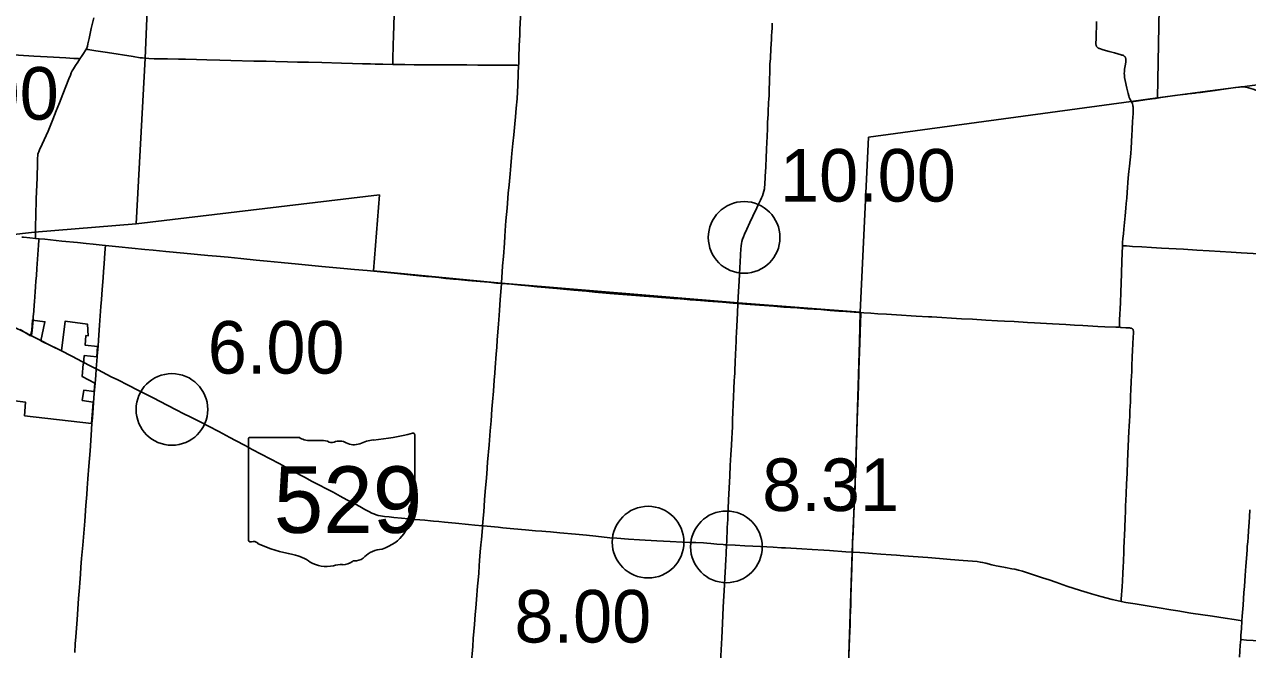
# Model space of a CAD drawing. Extents: x 1813937 to 1948437, y 826606 to 1022856.
# Drawn here: x 1864595 to 1890191, y 901785 to 914870 of the extents above; entities that cross this region are included whole.
import ezdxf

# ---------------------------------------------------------------- set-up
doc = ezdxf.new("R2010")
doc.units = 0
for name, color, linetype in [('Default', 7, 'Continuous'), ('GM_X_Corporation', 7, 'Continuous'), ('GM_X_County_Road', 7, 'Continuous'), ('GM_X_State_Route', 7, 'Continuous'), ('GM_X_State_Shield', 7, 'Continuous'), ('GM_X_Township', 7, 'Continuous'), ('GM_X_Township_Road', 7, 'Continuous')]:
    doc.layers.add(name, color=color, linetype=linetype)

msp = doc.modelspace()

# ---------------------------------------------------------------- linework, layer by layer
at = {"layer": 'Default'}
for centre in [(1879656, 910412), (1867681, 906811), (1877646, 904033), (1879285, 903935)]:
    msp.add_circle(centre, 750, dxfattribs=at)
at = {"layer": 'GM_X_Corporation'}
msp.add_lwpolyline([(1864504, 908482), (1864721, 908355), (1864749, 908472), (1864763, 908683), (1865022, 908648), (1864938, 908249), (1865371, 908041), (1865448, 908659), (1865916, 908595), (1865927, 908351), (1865880, 908356), (1865864, 908157), (1866127, 908131), (1866109, 907912), (1865846, 907937), (1865832, 907762), (1865826, 907765), (1865805, 907500), (1866068, 907363), (1866053, 907186), (1865836, 907213), (1865806, 907000), (1866036, 906960), (1866001, 906516), (1864597, 906679), (1864620, 906961), (1863278, 907134)], dxfattribs=at)
at = {"layer": 'GM_X_County_Road'}
for points in [[(1874936, 914014), (1874938, 914048), (1874941, 914179), (1874951, 914424), (1874959, 914654), (1874965, 914769), (1874973, 915014), (1874979, 915195), (1874985, 915309), (1874992, 915506), (1875003, 915785), (1875010, 915998), (1875017, 916211), (1875023, 916392), (1875029, 916556), (1875032, 916651)], [(1887765, 913249), (1887727, 913315), (1887714, 913344), (1887704, 913375), (1887691, 913422), (1887665, 913534), (1887630, 913694), (1887619, 913759), (1887613, 913807), (1887611, 913840), (1887613, 913888), (1887618, 913937), (1887628, 914002), (1887642, 914083), (1887645, 914109), (1887645, 914116), (1887646, 914123), (1887646, 914133), (1887645, 914141), (1887644, 914150), (1887642, 914158), (1887640, 914167), (1887636, 914175), (1887632, 914182), (1887627, 914190), (1887622, 914196), (1887616, 914202), (1887609, 914207), (1887602, 914212), (1887595, 914217), (1887580, 914224), (1887564, 914230), (1887548, 914235), (1887406, 914276), (1887295, 914306), (1887169, 914341), (1887090, 914365), (1887084, 914367), (1887075, 914371), (1887068, 914375), (1887061, 914378), (1887055, 914382), (1887049, 914387), (1887044, 914392), (1887038, 914398), (1887034, 914404), (1887030, 914411), (1887027, 914417), (1887024, 914426), (1887022, 914432), (1887021, 914441), (1887019, 914449), (1887019, 914457), (1887018, 914489), (1887021, 914555), (1887026, 914702), (1887028, 914801), (1887028, 914817), (1887031, 914931)], [(1865756, 914153), (1865805, 914223), (1865892, 914359)], [(1865892, 914359), (1865923, 914348), (1866091, 914319), (1866334, 914281), (1866869, 914196), (1867015, 914174), (1867067, 914169)], [(1863617, 914277), (1863633, 914276), (1863731, 914270), (1863927, 914257), (1864254, 914239), (1864467, 914227), (1864794, 914208), (1865071, 914190), (1865464, 914168), (1865627, 914160), (1865723, 914156), (1865756, 914153)], [(1867067, 914169), (1867113, 914163), (1867195, 914157), (1867310, 914153), (1867588, 914148), (1867818, 914144), (1867966, 914140), (1868195, 914136), (1868409, 914129), (1868687, 914123), (1868917, 914116), (1869393, 914104), (1869655, 914099), (1869852, 914094), (1870098, 914088), (1870311, 914082), (1870541, 914077), (1870820, 914070), (1871230, 914060), (1871459, 914053), (1871672, 914048), (1871738, 914046), (1871836, 914044), (1871934, 914041), (1872098, 914036), (1872301, 914032)], [(1872301, 914032), (1872328, 914032), (1872557, 914029), (1872754, 914028), (1872902, 914026), (1872984, 914025), (1873164, 914026), (1873377, 914026), (1873558, 914025), (1873853, 914022), (1874083, 914021), (1874345, 914019), (1874559, 914017), (1874755, 914017), (1874903, 914015), (1874936, 914014)], [(1874575, 909448), (1874576, 909471), (1874592, 909683), (1874602, 909814), (1874618, 910011), (1874638, 910289), (1874649, 910435), (1874657, 910550), (1874665, 910664), (1874672, 910762), (1874694, 911024), (1874719, 911335), (1874736, 911514), (1874757, 911743), (1874773, 911907), (1874789, 912086), (1874796, 912168), (1874817, 912380), (1874834, 912560), (1874858, 912788), (1874871, 912935), (1874887, 913115), (1874903, 913311), (1874912, 913459), (1874918, 913590), (1874929, 913835), (1874936, 914014)], [(1887573, 910239), (1887576, 910309), (1887583, 910390), (1887593, 910488), (1887601, 910586), (1887608, 910651), (1887628, 910863), (1887643, 911024), (1887652, 911122), (1887662, 911236), (1887671, 911350), (1887696, 911661), (1887708, 911791), (1887721, 911905), (1887735, 912036), (1887746, 912166), (1887754, 912281), (1887763, 912412), (1887770, 912557), (1887777, 912655), (1887780, 912687), (1887787, 912833), (1887793, 912931), (1887797, 912996), (1887800, 913061), (1887800, 913094), (1887798, 913127), (1887795, 913144), (1887792, 913160), (1887789, 913177), (1887781, 913208), (1887777, 913221), (1887775, 913228), (1887771, 913238), (1887765, 913249)], [(1887514, 908539), (1887512, 908543), (1887510, 908548), (1887510, 908552), (1887510, 908557), (1887510, 908573), (1887511, 908589), (1887515, 908687), (1887520, 908802), (1887526, 908916), (1887530, 909047), (1887538, 909260), (1887551, 909654), (1887559, 909916), (1887573, 910239)], [(1887573, 910239), (1887606, 910237), (1887655, 910234), (1887786, 910225), (1887982, 910215), (1888179, 910203), (1888392, 910190), (1888850, 910163), (1889128, 910146), (1889390, 910131), (1889620, 910119), (1889849, 910105), (1890061, 910092), (1890307, 910076), (1890560, 910061)], [(1874182, 904375), (1874196, 904531), (1874208, 904678), (1874215, 904776), (1874226, 904924), (1874245, 905169), (1874255, 905300), (1874268, 905463), (1874288, 905708), (1874317, 906068), (1874342, 906362), (1874359, 906575), (1874377, 906820), (1874389, 906968), (1874409, 907197), (1874426, 907426), (1874437, 907573), (1874446, 907687), (1874468, 907965), (1874479, 908113), (1874491, 908260), (1874515, 908603), (1874521, 908685), (1874535, 908882), (1874552, 909111), (1874569, 909356), (1874575, 909448)], [(1879526, 909029), (1879687, 909018), (1879883, 909003), (1880276, 908972), (1880489, 908955), (1880767, 908936), (1880980, 908919), (1881258, 908900), (1881454, 908885), (1881635, 908870), (1881782, 908859), (1881962, 908846), (1882060, 908840), (1882101, 908837)], [(1882101, 908837), (1882158, 908833), (1882306, 908824), (1882453, 908814), (1882633, 908802), (1882846, 908788), (1883256, 908765), (1883518, 908752), (1883567, 908749), (1883584, 908750), (1884207, 908711), (1884436, 908699), (1884715, 908683), (1884961, 908668), (1885108, 908660), (1885305, 908649), (1885583, 908634), (1885731, 908626), (1886108, 908604), (1886386, 908587), (1886567, 908577), (1886747, 908566), (1887058, 908550), (1887206, 908543), (1887438, 908533), (1887472, 908532), (1887486, 908533), (1887493, 908534), (1887500, 908535), (1887514, 908539)], [(1887544, 902792), (1887547, 902826), (1887548, 902842), (1887566, 903104), (1887572, 903219), (1887582, 903382), (1887589, 903513), (1887593, 903627), (1887601, 903838), (1887605, 903904), (1887610, 904051), (1887615, 904182), (1887621, 904329), (1887630, 904558), (1887634, 904656), (1887640, 904803), (1887645, 904901), (1887650, 905049), (1887658, 905245), (1887669, 905474), (1887679, 905720), (1887709, 906359), (1887713, 906457), (1887719, 906572), (1887725, 906670), (1887730, 906785), (1887735, 906883), (1887739, 906965), (1887745, 907112), (1887749, 907210), (1887758, 907407), (1887767, 907603), (1887771, 907718), (1887778, 907915), (1887784, 908045), (1887796, 908324), (1887802, 908406), (1887804, 908439), (1887803, 908448), (1887802, 908456), (1887801, 908465), (1887798, 908473), (1887795, 908481), (1887790, 908488), (1887784, 908495), (1887778, 908500), (1887771, 908505), (1887763, 908509), (1887755, 908512), (1887746, 908514), (1887738, 908515), (1887729, 908516), (1887647, 908519), (1887549, 908524), (1887540, 908525), (1887533, 908527), (1887525, 908530), (1887520, 908533), (1887515, 908537), (1887514, 908539)], [(1866073, 907360), (1866086, 907523), (1866096, 907664)], [(1866041, 906948), (1866050, 907054), (1866056, 907148)], [(1866056, 907148), (1866073, 907360)], [(1866008, 906520), (1866017, 906638), (1866041, 906948)], [(1865647, 901725), (1865659, 901905), (1865670, 902052), (1865696, 902413), (1865727, 902855), (1865745, 903084), (1865752, 903182), (1865766, 903362), (1865778, 903509), (1865792, 903689), (1865814, 903968), (1865855, 904475), (1865881, 904802), (1865897, 905032), (1865908, 905162), (1865921, 905359), (1865941, 905621), (1865967, 905948), (1865990, 906276), (1866008, 906520)], [(1890074, 902387), (1890082, 902487), (1890099, 902716), (1890116, 902977), (1890125, 903108), (1890143, 903337), (1890157, 903533), (1890176, 903778), (1890182, 903877), (1890186, 903942), (1890195, 904040), (1890202, 904138), (1890210, 904269), (1890222, 904449), (1890231, 904562), (1890238, 904709)], [(1873945, 901475), (1873975, 901851), (1873988, 902014), (1874013, 902308), (1874028, 902521), (1874039, 902652), (1874053, 902832), (1874078, 903109), (1874089, 903240), (1874101, 903387), (1874113, 903534), (1874120, 903649), (1874135, 903828), (1874147, 903976), (1874157, 904090), (1874178, 904335), (1874182, 904375)], [(1879288, 903976), (1879469, 903967), (1879671, 903957), (1879835, 903950), (1879999, 903940), (1880261, 903926), (1880441, 903916), (1880523, 903911), (1880867, 903891), (1881080, 903878), (1881325, 903862), (1881440, 903855), (1881784, 903832), (1881914, 903824), (1881921, 903823)], [(1881921, 903823), (1882078, 903814), (1882176, 903807), (1882340, 903797), (1882520, 903785), (1882733, 903769), (1882848, 903760), (1882995, 903749), (1883191, 903735), (1883502, 903711), (1883747, 903690), (1883977, 903673), (1884238, 903651), (1884533, 903625), (1884598, 903617), (1884647, 903608), (1884711, 903593), (1884838, 903560), (1884933, 903537), (1885013, 903520), (1885126, 903500), (1885256, 903478), (1885320, 903466), (1885400, 903447), (1885480, 903425), (1885605, 903385), (1885901, 903288), (1886041, 903241), (1886181, 903194), (1886413, 903113), (1886694, 903021), (1886835, 902976), (1886929, 902948), (1887119, 902897), (1887357, 902836), (1887453, 902812), (1887544, 902792)], [(1887544, 902792), (1887549, 902791), (1887645, 902772), (1887839, 902740), (1888131, 902692), (1888341, 902657), (1888584, 902617), (1888730, 902593), (1889005, 902549), (1889460, 902481), (1889720, 902443), (1889914, 902413), (1889995, 902400), (1890074, 902387)], [(1890074, 902387), (1890063, 902219), (1890054, 902087), (1890051, 901992)], [(1890021, 901627), (1890040, 901877), (1890045, 901935), (1890051, 901992)], [(1890051, 901992), (1890172, 901983), (1890581, 901959)]]:
    msp.add_lwpolyline(points, dxfattribs=at)
at = {"layer": 'GM_X_State_Route'}
for points in [[(1879315, 904571), (1879331, 904914), (1879354, 905422), (1879365, 905635), (1879379, 905864), (1879392, 906060), (1879402, 906208), (1879408, 906323), (1879413, 906454), (1879416, 906569), (1879421, 906782), (1879425, 906880), (1879437, 907109), (1879441, 907207), (1879442, 907224), (1879444, 907273), (1879448, 907387), (1879450, 907436), (1879452, 907469), (1879459, 907599), (1879469, 907827), (1879474, 907942), (1879482, 908122), (1879486, 908220), (1879490, 908302), (1879497, 908432), (1879503, 908547), (1879510, 908694), (1879516, 908825), (1879526, 909029), (1879533, 909169), (1879551, 909497), (1879565, 909792), (1879570, 909890), (1879578, 910054), (1879586, 910168), (1879593, 910233), (1879600, 910282), (1879611, 910329), (1879624, 910376), (1879640, 910422), (1879665, 910483), (1879712, 910587), (1879773, 910722), (1879837, 910855), (1879922, 911032), (1879958, 911106), (1880000, 911195), (1880021, 911240), (1880039, 911285), (1880055, 911332), (1880068, 911380), (1880079, 911428), (1880083, 911461), (1880087, 911510), (1880095, 911690), (1880107, 911887), (1880117, 912084), (1880126, 912247), (1880133, 912411), (1880136, 912510), (1880144, 912706), (1880148, 912821), (1880156, 912985), (1880160, 913050), (1880169, 913230), (1880174, 913311), (1880177, 913377), (1880180, 913475), (1880188, 913705), (1880192, 913885), (1880193, 913934), (1880193, 913966), (1880195, 913998), (1880197, 914047), (1880200, 914096), (1880205, 914160), (1880209, 914226), (1880213, 914307), (1880218, 914388), (1880221, 914437), (1880224, 914486), (1880226, 914535), (1880231, 914616), (1880237, 914731), (1880240, 914780), (1880242, 914845), (1880245, 914894)], [(1864348, 908554), (1864369, 908543), (1864598, 908427), (1864712, 908367), (1864739, 908354)], [(1864739, 908354), (1864938, 908254)], [(1864938, 908254), (1865115, 908164), (1865285, 908079)], [(1865285, 908079), (1865354, 908043), (1865586, 907925), (1865811, 907809), (1865839, 907794)], [(1865839, 907794), (1865957, 907734), (1866096, 907664), (1866140, 907639), (1866413, 907497), (1866546, 907431), (1866764, 907319), (1866970, 907217), (1867291, 907051), (1867583, 906900), (1867787, 906795), (1867919, 906729), (1868079, 906646), (1868284, 906542), (1868445, 906459), (1868663, 906346), (1868896, 906225), (1869012, 906163), (1869084, 906124), (1869142, 906093), (1869213, 906053), (1869358, 905975), (1869924, 905676), (1870228, 905514), (1870459, 905390), (1870618, 905305), (1871054, 905076), (1871199, 904999), (1871343, 904921), (1871430, 904875), (1871617, 904776), (1871718, 904720), (1871804, 904673), (1871862, 904643), (1871907, 904623), (1871953, 904606), (1872000, 904593), (1872048, 904583), (1872129, 904571), (1872226, 904561), (1872324, 904552), (1872487, 904537), (1872634, 904522), (1872764, 904510), (1872977, 904491), (1873091, 904478), (1873156, 904471), (1873270, 904462), (1873384, 904451), (1873613, 904430), (1873891, 904403), (1874021, 904391), (1874182, 904375), (1874200, 904373), (1874510, 904345), (1874608, 904335), (1874836, 904314), (1875081, 904292), (1875293, 904272), (1875423, 904262), (1875505, 904256), (1875603, 904246), (1875799, 904228), (1876126, 904199), (1876354, 904177), (1876550, 904158), (1876844, 904126), (1876991, 904114), (1877236, 904098), (1877466, 904084), (1877826, 904061), (1878105, 904047), (1878367, 904032), (1878514, 904026), (1878645, 904023), (1878809, 904017), (1878875, 904013), (1878957, 904006), (1879087, 903994), (1879218, 903983), (1879251, 903980), (1879288, 903976)], [(1879245, 903138), (1879247, 903162), (1879259, 903408), (1879264, 903523), (1879272, 903686), (1879277, 903768), (1879281, 903850), (1879286, 903931), (1879288, 903976), (1879292, 904046), (1879295, 904128), (1879299, 904243), (1879304, 904341), (1879313, 904504), (1879315, 904571)], [(1878988, 898033), (1879010, 898444), (1879024, 898673), (1879042, 899001), (1879050, 899214), (1879055, 899345), (1879062, 899493), (1879072, 899673), (1879083, 899919), (1879099, 900263), (1879107, 900460), (1879124, 900787), (1879127, 900836), (1879141, 901098), (1879156, 901426), (1879168, 901655), (1879188, 902032), (1879203, 902327), (1879220, 902671), (1879245, 903138)]]:
    msp.add_lwpolyline(points, dxfattribs=at)
at = {"layer": 'GM_X_State_Shield'}
for p, q in [((1869281, 906191), (1869281, 904078)), ((1870335, 906227), (1869315, 906227)), ((1872762, 905174), (1872762, 906280)), ((1872761, 905174), (1872762, 905174))]:
    msp.add_line(p, q, dxfattribs=at)
for centre, major_axis, start_param, end_param in [((1869321, 906195), (40.3, 0), 1.712693, 3.28349), ((1870577, 906473), (391, 0), 4.042523, 4.731795), ((1870707, 905041), (1404, 0), 1.404758, 1.657858), ((1871026, 906206), (113, 0), 3.836095, 5.185415), ((1871191, 905962), (235, 0), 0.950623, 2.079405), ((1871494, 906297), (282, 0), 4.081561, 5.145723), ((1871993, 905582), (743, 0), 1.699011, 2.107814), ((1871522, 909108), (3691, 0), 4.814394, 5.042369), ((1872723, 906284), (38.7, 0), 6.141152, 7.989035), ((1872753, 905093), (60, 0), 1.883978, 3.671073), ((1872720, 905170), (41.5, 0), 5.05454, 6.418171), ((1872900, 904711), (262, 0), 2.387724, 3.262537), ((1872371, 904953), (360, 0), 5.934695, 6.695948), ((1871729, 904571), (923, 0), 5.101752, 6.440018), ((1869321, 904073), (40.7, 0), 3.00124, 4.508301), ((1869328, 904289), (310, 0), 4.665946, 4.897461), ((1869391, 903956), (112, 0), 0.519207, 1.627899), ((1870804, 905854), (2665, 0), 4.195997, 4.488961), ((1872118, 903484), (506, 0), 1.647645, 2.488434), ((1870010, 903128), (834, 0), 0.823519, 1.323587), ((1870912, 903945), (529, 0), 4.026481, 4.996735), ((1871217, 903215), (435, 0), 1.495662, 1.94098), ((1871256, 903787), (282, 0), 4.691044, 5.507374), ((1871511, 903582), (79.4, 0), 1.147584, 2.315152), ((1871477, 903873), (298, 0), 4.937069, 5.64225)]:
    msp.add_ellipse(centre, major_axis=major_axis, ratio=0.8, start_param=start_param, end_param=end_param, dxfattribs=at)
at = {"layer": 'GM_X_Township'}
for points in [[(1862529, 931646), (1862452, 926319), (1863806, 926284), (1864501, 926257), (1864642, 926260), (1866861, 926186), (1867410, 926171), (1867588, 926156), (1867590, 926005), (1867433, 922134), (1867234, 916844), (1867123, 914163), (1866935, 910696)], [(1891076, 913698), (1890078, 913562), (1889943, 913553), (1889411, 913481), (1888309, 913332), (1888362, 916340), (1888657, 926560), (1888668, 926924), (1888752, 929651), (1891412, 929604)], [(1880714, 883463), (1880836, 885744), (1880863, 886256), (1881338, 891636), (1881703, 897023), (1881803, 900282), (1881806, 900375), (1881918, 903829), (1881985, 905459), (1882074, 908232), (1882082, 908847), (1882260, 912507), (1887758, 913255), (1888309, 913332)], [(1853740, 885139), (1853912, 887891), (1854256, 893376), (1854601, 899118), (1855968, 899037), (1856227, 902512), (1856354, 904189), (1858556, 904033), (1863007, 903717), (1863265, 907135), (1863306, 907714), (1863375, 908580), (1863406, 908966), (1863544, 910397), (1864246, 910459), (1864806, 910520), (1866935, 910696), (1872022, 911301), (1871903, 909711), (1873264, 909583), (1874571, 909455), (1879532, 909040), (1882082, 908847)]]:
    msp.add_lwpolyline(points, dxfattribs=at)
at = {"layer": 'GM_X_Township_Road'}
for points in [[(1872301, 914032), (1872302, 914059), (1872305, 914141), (1872314, 914436), (1872318, 914633), (1872324, 914846), (1872332, 915076), (1872339, 915305), (1872343, 915486), (1872349, 915683), (1872358, 915994), (1872364, 916240), (1872368, 916404), (1872373, 916650), (1872374, 916692)], [(1865892, 914359), (1865912, 914415), (1865924, 914463), (1865948, 914575), (1865994, 914783), (1866045, 915007)], [(1864825, 910451), (1864824, 910544), (1864825, 910610), (1864828, 910708), (1864831, 910807), (1864836, 910987), (1864839, 911086), (1864843, 911217), (1864848, 911365), (1864858, 911661), (1864867, 911973), (1864870, 912075), (1864872, 912120), (1864877, 912153), (1864883, 912177), (1864893, 912203), (1864911, 912246), (1864965, 912366), (1865088, 912635), (1865134, 912741), (1865189, 912878), (1865261, 913061), (1865326, 913230), (1865398, 913413), (1865525, 913734), (1865555, 913811), (1865574, 913856), (1865596, 913900), (1865620, 913943), (1865665, 914012), (1865711, 914080), (1865756, 914153)], [(1888253, 913319), (1888267, 913321), (1888379, 913338), (1888476, 913353), (1888573, 913367), (1888670, 913380), (1888784, 913395), (1888914, 913412), (1888946, 913417), (1889027, 913425), (1889092, 913433), (1889125, 913436), (1889206, 913447), (1889303, 913462), (1889514, 913490), (1889693, 913516), (1889936, 913551), (1890001, 913559), (1890021, 913560)], [(1890021, 913560), (1890050, 913562), (1890083, 913563), (1890116, 913561), (1890149, 913558), (1890181, 913552), (1890213, 913545), (1890260, 913531), (1890306, 913514), (1890398, 913477), (1890444, 913461), (1890490, 913447), (1890538, 913435), (1890586, 913428), (1890668, 913421), (1890831, 913410), (1891075, 913399)], [(1887765, 913249), (1887910, 913272), (1888040, 913291), (1888253, 913319)], [(1864543, 910418), (1864576, 910414), (1864707, 910401), (1864824, 910390)], [(1864775, 908685), (1864780, 908760), (1864788, 908858), (1864799, 909005), (1864802, 909054), (1864811, 909185), (1864816, 909267), (1864826, 909382), (1864836, 909497), (1864844, 909612), (1864856, 909760), (1864863, 909858), (1864870, 909957), (1864882, 910154), (1864889, 910252), (1864897, 910351), (1864900, 910383)], [(1864824, 910390), (1864825, 910451)], [(1864824, 910390), (1864838, 910389), (1864900, 910383)], [(1864900, 910383), (1865018, 910372), (1865377, 910336), (1865704, 910305), (1865884, 910286), (1866031, 910269), (1866219, 910251), (1866288, 910244)], [(1866134, 908133), (1866144, 908262), (1866165, 908572), (1866195, 908964), (1866206, 909111), (1866219, 909322), (1866240, 909567), (1866248, 909698), (1866261, 909862), (1866268, 909976), (1866283, 910182), (1866288, 910244)], [(1866288, 910244), (1866572, 910216), (1867111, 910162), (1867291, 910145), (1867552, 910119), (1867928, 910082), (1868434, 910036), (1868614, 910018), (1868859, 909996), (1869121, 909971), (1869447, 909937), (1869676, 909914), (1869970, 909886), (1870329, 909851), (1870819, 909806), (1871277, 909764), (1871505, 909742), (1871770, 909718)], [(1871770, 909718), (1872401, 909655), (1872859, 909610), (1873006, 909596), (1873120, 909585), (1873267, 909570), (1873414, 909555), (1873577, 909538), (1873675, 909529), (1873871, 909512), (1874133, 909488), (1874313, 909472), (1874476, 909457), (1874575, 909448)], [(1874575, 909448), (1874688, 909438), (1874786, 909431), (1874983, 909414), (1875146, 909398), (1875326, 909381), (1875734, 909342), (1875946, 909322), (1876094, 909309), (1876355, 909284), (1876535, 909267), (1876845, 909239), (1877205, 909207), (1877565, 909180), (1877762, 909167), (1877925, 909154), (1878105, 909141), (1878187, 909135), (1878318, 909123), (1878398, 909116), (1878529, 909105), (1878643, 909096), (1878741, 909089), (1878905, 909077), (1879200, 909056), (1879429, 909037), (1879511, 909030), (1879526, 909029)], [(1864739, 908354), (1864740, 908359), (1864749, 908417), (1864755, 908465), (1864775, 908685)], [(1881988, 905448), (1881991, 905523), (1881998, 905654), (1882004, 905835), (1882009, 906097), (1882018, 906343), (1882032, 906788), (1882042, 907082), (1882048, 907327), (1882055, 907557), (1882058, 907639), (1882063, 907819), (1882070, 908016), (1882077, 908197), (1882084, 908426), (1882093, 908640), (1882100, 908804), (1882101, 908837)], [(1866096, 907664), (1866116, 907913)], [(1866116, 907913), (1866117, 907927), (1866134, 908133)], [(1881921, 903823), (1881922, 903949), (1881927, 904064), (1881935, 904211), (1881945, 904441), (1881954, 904638), (1881971, 905015), (1881978, 905245), (1881983, 905359), (1881988, 905448)], [(1881848, 901653), (1881856, 901833), (1881862, 902014), (1881868, 902178), (1881872, 902293), (1881874, 902375), (1881877, 902473), (1881882, 902588), (1881886, 902719), (1881891, 902867), (1881899, 903113), (1881905, 903293), (1881912, 903506), (1881920, 903769), (1881921, 903823)]]:
    msp.add_lwpolyline(points, dxfattribs=at)

# ---------------------------------------------------------------- texts
at = {"layer": 'Default'}
for s, p in [('8.00', (1862450, 912877)), ('10.00', (1880406, 911162)), ('6.00', (1868431, 907561)), ('8.31', (1880035, 904685)), ('8.00', (1874849, 901932))]:
    msp.add_text(s, height=1100, dxfattribs=at).set_placement(p)
at = {"layer": 'GM_X_State_Shield'}
msp.add_text('529', height=1392.2, dxfattribs=at).set_placement((1869813, 904227))

doc.saveas('drawing.dxf')
